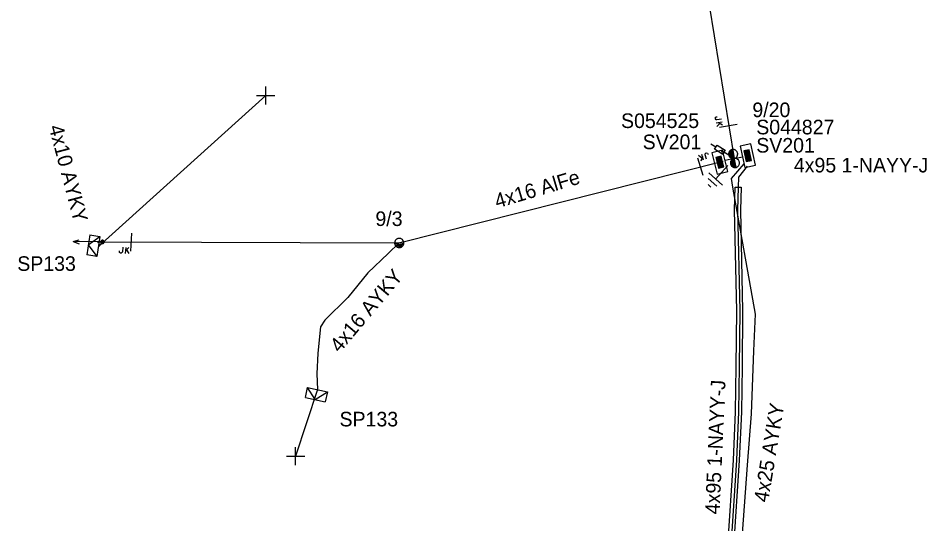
# Model space of a CAD drawing. Extents: x -717562 to -713845, y -1151196 to -1143903.
# Drawn here: x -716997.4 to -716935, y -1145301 to -1145266.3 of the extents above; entities that cross this region are included whole.
import ezdxf

# ---------------------------------------------------------------- set-up
doc = ezdxf.new("R2010")
doc.units = 0
for name, color, linetype in [('Vrstva 1', 7, 'Continuous'), ('Vrstva 12', 7, 'Continuous'), ('Vrstva 13', 7, 'Continuous'), ('Vrstva 14', 7, 'Continuous'), ('Vrstva 15', 7, 'Continuous'), ('Vrstva 16', 7, 'Continuous'), ('Vrstva 18', 7, 'Continuous'), ('Vrstva 2', 7, 'Continuous'), ('Vrstva 20', 7, 'Continuous'), ('Vrstva 28', 7, 'Continuous'), ('Vrstva 29', 7, 'Continuous'), ('Vrstva 30', 7, 'Continuous'), ('Vrstva 31', 7, 'Continuous'), ('Vrstva 33', 7, 'Continuous'), ('Vrstva 34', 7, 'Continuous'), ('Vrstva 5', 7, 'Continuous'), ('Vrstva 52', 7, 'Continuous'), ('Vrstva 54', 7, 'Continuous'), ('Vrstva 59', 7, 'Continuous'), ('Vrstva 6', 7, 'Continuous'), ('Vrstva 8', 7, 'Continuous'), ('Vrstva 9', 7, 'Continuous')]:
    doc.layers.add(name, color=color, linetype=linetype)

# ---------------------------------------------------------------- blocks, each defined once
blk = doc.blocks.new('NN440')
at = {"layer": 'Vrstva 2'}
for points in [[(0.63, 0), (0.63, 0.06), (0.62, 0.13), (0.6, 0.19), (0.58, 0.25), (0.55, 0.31), (0.51, 0.37), (0.47, 0.42), (0.42, 0.46), (0.37, 0.51), (0.32, 0.54), (0.26, 0.57), (0.2, 0.59), (0.13, 0.61), (0.07, 0.62), (0, 0.63), (-0.06, 0.62), (-0.13, 0.61), (-0.19, 0.59), (-0.26, 0.57), (-0.31, 0.54), (-0.37, 0.51), (-0.42, 0.46), (-0.47, 0.42), (-0.51, 0.37), (-0.54, 0.31), (-0.57, 0.25), (-0.6, 0.19), (-0.62, 0.13), (-0.63, 0.06), (-0.63, 0), (-0.63, -0.07), (-0.62, -0.14), (-0.6, -0.2), (-0.57, -0.26), (-0.54, -0.32), (-0.51, -0.37), (-0.47, -0.43), (-0.42, -0.47), (-0.37, -0.51), (-0.31, -0.55), (-0.26, -0.58), (-0.19, -0.6), (-0.13, -0.62), (-0.06, -0.63), (0, -0.63), (0.07, -0.63), (0.13, -0.62), (0.2, -0.6), (0.26, -0.58), (0.32, -0.55), (0.37, -0.51), (0.42, -0.47), (0.47, -0.43), (0.51, -0.37), (0.55, -0.32), (0.58, -0.26), (0.6, -0.2), (0.62, -0.14), (0.63, -0.07), (0.63, 0)], [(-0.63, 0), (0.63, 0)], [(-0.6, -0.18), (0.57, -0.18)], [(-0.51, -0.32), (0.5, -0.32)], [(-0.37, -0.47), (0.35, -0.47)]]:
    blk.add_lwpolyline(points, dxfattribs=at)
blk = doc.blocks.new('NN450')
at = {"layer": 'Vrstva 2'}
for points in [[(0, 0), (0, 0.07), (-0.01, 0.13), (-0.03, 0.19), (-0.05, 0.25), (-0.08, 0.31), (-0.12, 0.37), (-0.16, 0.42), (-0.21, 0.46), (-0.26, 0.51), (-0.31, 0.54), (-0.37, 0.57), (-0.43, 0.59), (-0.5, 0.61), (-0.56, 0.62), (-0.63, 0.62), (-0.69, 0.62), (-0.75, 0.61), (-0.82, 0.59), (-0.88, 0.57), (-0.94, 0.54), (-0.99, 0.51), (-1.04, 0.46), (-1.09, 0.42), (-1.13, 0.37), (-1.17, 0.31), (-1.2, 0.25), (-1.22, 0.19), (-1.24, 0.13), (-1.25, 0.07), (-1.25, 0), (-1.25, -0.07), (-1.24, -0.13), (-1.22, -0.19), (-1.2, -0.25), (-1.17, -0.31), (-1.13, -0.37), (-1.09, -0.42), (-1.04, -0.46), (-0.99, -0.51), (-0.94, -0.54), (-0.88, -0.57), (-0.82, -0.59), (-0.75, -0.61), (-0.69, -0.62), (-0.62, -0.63), (-0.56, -0.62), (-0.5, -0.61), (-0.43, -0.59), (-0.37, -0.57), (-0.31, -0.54), (-0.26, -0.51), (-0.21, -0.46), (-0.16, -0.42), (-0.12, -0.37), (-0.08, -0.31), (-0.05, -0.25), (-0.03, -0.19), (-0.01, -0.13), (0, -0.07), (0, 0)], [(1.25, 0), (1.25, 0.07), (1.24, 0.13), (1.22, 0.19), (1.2, 0.25), (1.17, 0.31), (1.13, 0.37), (1.09, 0.42), (1.04, 0.46), (0.99, 0.51), (0.94, 0.54), (0.88, 0.57), (0.82, 0.59), (0.75, 0.61), (0.69, 0.62), (0.62, 0.62), (0.56, 0.62), (0.5, 0.61), (0.43, 0.59), (0.37, 0.57), (0.31, 0.54), (0.26, 0.51), (0.21, 0.46), (0.16, 0.42), (0.12, 0.37), (0.08, 0.31), (0.05, 0.25), (0.03, 0.19), (0.01, 0.13), (0, 0.07), (0, 0), (0, -0.07), (0.01, -0.13), (0.03, -0.19), (0.05, -0.25), (0.08, -0.31), (0.12, -0.37), (0.16, -0.42), (0.21, -0.46), (0.26, -0.51), (0.31, -0.54), (0.37, -0.57), (0.43, -0.59), (0.5, -0.61), (0.56, -0.62), (0.63, -0.63), (0.69, -0.62), (0.75, -0.61), (0.82, -0.59), (0.88, -0.57), (0.94, -0.54), (0.99, -0.51), (1.04, -0.46), (1.09, -0.42), (1.13, -0.37), (1.17, -0.31), (1.2, -0.25), (1.22, -0.19), (1.24, -0.13), (1.25, -0.07), (1.25, 0)], [(-1.25, 0), (1.25, 0)], [(-1.23, -0.16), (-0.02, -0.16)], [(-1.16, -0.32), (-0.09, -0.32)], [(-1.03, -0.47), (-0.22, -0.47)], [(0.02, -0.16), (1.23, -0.16)], [(0.09, -0.32), (1.16, -0.32)], [(0.22, -0.47), (1.03, -0.47)]]:
    blk.add_lwpolyline(points, dxfattribs=at)
blk = doc.blocks.new('NN560')
at = {"layer": 'Vrstva 2'}
for points in [[(1.999, -0.001), (1.59, 0.141)], [(0, -0.001), (1.999, -0.001)], [(1.999, -0.001), (1.59, -0.134)]]:
    blk.add_lwpolyline(points, dxfattribs=at)
blk = doc.blocks.new('NN840')
at = {"layer": 'Vrstva 15'}
for points in [[(0.003, 0.619), (0.003, -0.631)], [(-0.538, -0.385), (-0.538, -0.71)], [(-0.332, -0.385), (-0.332, -0.798)], [(-0.332, -0.641), (-0.125, -0.385)], [(-0.263, -0.557), (-0.091, -0.798)], [(-0.745, -0.71), (-0.745, -0.66)], [(-0.73, -0.764), (-0.745, -0.71)], [(-0.657, -0.798), (-0.73, -0.764)], [(-0.627, -0.798), (-0.657, -0.798)], [(-0.558, -0.764), (-0.627, -0.798)], [(-0.538, -0.71), (-0.558, -0.764)]]:
    blk.add_lwpolyline(points, dxfattribs=at)
blk = doc.blocks.new('NN800')
at = {"layer": 'Vrstva 1'}
for points in [[(-0.442, 0.442), (0.442, -0.442)], [(-0.442, -0.442), (0.442, 0.442)]]:
    blk.add_lwpolyline(points, dxfattribs=at)
blk = doc.blocks.new('NN820')
at = {"layer": 'Vrstva 13'}
for points in [[(-0.003, 0.004), (-0.003, -1.049)], [(-0.165, -0.813), (0.165, -0.813)], [(-0.165, -1.473), (-0.165, -0.813)], [(-0.003, -1.049), (-0.062, -0.926)], [(-0.003, -1.049), (0.057, -0.926)], [(0.165, -0.813), (0.165, -1.473)], [(0.165, -1.473), (-0.165, -1.473)], [(-0.003, -1.473), (-0.003, -1.871)]]:
    blk.add_lwpolyline(points, dxfattribs=at)
blk = doc.blocks.new('NN620')
at = {"layer": 'Vrstva 8'}
for points in [[(0.752, 0.004), (-0.748, 0.004)], [(-0.748, 0.004), (-0.748, -0.746)], [(0.752, -0.746), (0.752, 0.004)], [(0.368, -0.18), (-0.376, -0.18)], [(-0.376, -0.18), (-0.376, -0.558)], [(-0.376, -0.558), (0.368, -0.558)], [(0.321, -0.227), (-0.329, -0.227)], [(-0.329, -0.227), (-0.329, -0.51)], [(-0.329, -0.51), (0.321, -0.51)], [(0.274, -0.274), (-0.281, -0.274)], [(-0.281, -0.274), (-0.281, -0.463)], [(-0.281, -0.463), (0.274, -0.463)], [(0.227, -0.321), (-0.234, -0.321)], [(-0.234, -0.321), (-0.234, -0.416)], [(-0.234, -0.416), (0.227, -0.416)], [(-0.193, -0.369), (0.185, -0.369)], [(0.227, -0.416), (0.227, -0.321)], [(0.274, -0.463), (0.274, -0.274)], [(0.321, -0.51), (0.321, -0.227)], [(0.368, -0.558), (0.368, -0.18)], [(-0.748, -0.746), (0.752, -0.746)]]:
    blk.add_lwpolyline(points, dxfattribs=at)
blk = doc.blocks.new('NN630')
at = {"layer": 'Vrstva 9'}
for points in [[(-0.003, -0.7), (-0.703, 0)], [(-0.703, -0.7), (-0.703, 0), (0.697, 0), (0.697, -0.7)], [(-0.003, -0.7), (0.697, 0)], [(-0.703, -0.7), (0.697, -0.7)]]:
    blk.add_lwpolyline(points, dxfattribs=at)
blk = doc.blocks.new('NN810')
at = {"layer": 'Vrstva 14'}
for points in [[(0.004, -0.64), (0.004, -1.89)], [(0.629, -1.89), (-0.621, -1.89)], [(0.388, -2.2), (-0.399, -2.2)], [(0.004, -2.515), (-0.124, -2.515)], [(0.137, -2.515), (0.004, -2.515)]]:
    blk.add_lwpolyline(points, dxfattribs=at)
blk = doc.blocks.new('NN500')
at = {"layer": 'Vrstva 2'}
for points in [[(0, -0.24), (0.02, -0.23), (0.05, -0.23), (0.07, -0.22), (0.09, -0.22), (0.12, -0.2), (0.14, -0.19), (0.16, -0.18), (0.17, -0.16), (0.19, -0.14), (0.2, -0.12), (0.21, -0.1), (0.22, -0.07), (0.23, -0.05), (0.23, -0.02), (0.23, 0), (0.23, 0.02), (0.23, 0.05), (0.22, 0.07), (0.21, 0.1), (0.2, 0.12), (0.19, 0.14), (0.17, 0.16), (0.16, 0.17), (0.14, 0.19), (0.12, 0.2), (0.09, 0.21), (0.07, 0.22), (0.05, 0.23), (0.02, 0.23), (0, 0.23), (-0.03, 0.23), (-0.05, 0.23), (-0.07, 0.22), (-0.1, 0.21), (-0.12, 0.2), (-0.14, 0.19), (-0.16, 0.17), (-0.18, 0.16), (-0.19, 0.14), (-0.2, 0.12), (-0.22, 0.1), (-0.22, 0.07), (-0.23, 0.05), (-0.23, 0.02), (-0.24, 0), (-0.23, -0.02), (-0.23, -0.05), (-0.22, -0.07), (-0.22, -0.1), (-0.2, -0.12), (-0.19, -0.14), (-0.18, -0.16), (-0.16, -0.18), (-0.14, -0.19), (-0.12, -0.2), (-0.1, -0.22), (-0.07, -0.22), (-0.05, -0.23), (-0.03, -0.23), (0, -0.24)], [(0, -0.24), (0.02, -0.23), (0.05, -0.23), (0.07, -0.22), (0.09, -0.22), (0.12, -0.2), (0.14, -0.19), (0.16, -0.18), (0.17, -0.16), (0.19, -0.14), (0.2, -0.12), (0.21, -0.1), (0.22, -0.07), (0.23, -0.05), (0.23, -0.02), (0.23, 0), (0.23, 0.02), (0.23, 0.05), (0.22, 0.07), (0.21, 0.1), (0.2, 0.12), (0.19, 0.14), (0.17, 0.16), (0.16, 0.17), (0.14, 0.19), (0.12, 0.2), (0.09, 0.21), (0.07, 0.22), (0.05, 0.23), (0.02, 0.23), (0, 0.23), (-0.03, 0.23), (-0.05, 0.23), (-0.07, 0.22), (-0.1, 0.21), (-0.12, 0.2), (-0.14, 0.19), (-0.16, 0.17), (-0.18, 0.16), (-0.19, 0.14), (-0.2, 0.12), (-0.22, 0.1), (-0.22, 0.07), (-0.23, 0.05), (-0.23, 0.02), (-0.24, 0), (-0.23, -0.02), (-0.23, -0.05), (-0.22, -0.07), (-0.22, -0.1), (-0.2, -0.12), (-0.19, -0.14), (-0.18, -0.16), (-0.16, -0.18), (-0.14, -0.19), (-0.12, -0.2), (-0.1, -0.22), (-0.07, -0.22), (-0.05, -0.23), (-0.03, -0.23), (0, -0.24)], [(0, -0.21), (0.02, -0.2), (0.04, -0.2), (0.06, -0.2), (0.08, -0.19), (0.1, -0.18), (0.12, -0.17), (0.14, -0.15), (0.15, -0.14), (0.16, -0.12), (0.18, -0.1), (0.19, -0.08), (0.19, -0.06), (0.2, -0.04), (0.2, -0.02), (0.2, 0), (0.2, 0.02), (0.2, 0.04), (0.19, 0.06), (0.19, 0.08), (0.18, 0.1), (0.16, 0.12), (0.15, 0.14), (0.14, 0.15), (0.12, 0.17), (0.1, 0.18), (0.08, 0.19), (0.06, 0.19), (0.04, 0.2), (0.02, 0.2), (0, 0.2), (-0.02, 0.2), (-0.04, 0.2), (-0.06, 0.19), (-0.08, 0.19), (-0.1, 0.18), (-0.12, 0.17), (-0.14, 0.15), (-0.15, 0.14), (-0.17, 0.12), (-0.18, 0.1), (-0.19, 0.08), (-0.2, 0.06), (-0.2, 0.04), (-0.21, 0.02), (-0.21, 0), (-0.21, -0.02), (-0.2, -0.04), (-0.2, -0.06), (-0.19, -0.08), (-0.18, -0.1), (-0.17, -0.12), (-0.15, -0.14), (-0.14, -0.15), (-0.12, -0.17), (-0.1, -0.18), (-0.08, -0.19), (-0.06, -0.2), (-0.04, -0.2), (-0.02, -0.2), (0, -0.21)], [(0, -0.18), (0.02, -0.18), (0.04, -0.17), (0.05, -0.17), (0.07, -0.16), (0.09, -0.15), (0.1, -0.14), (0.12, -0.13), (0.13, -0.12), (0.14, -0.1), (0.15, -0.09), (0.16, -0.07), (0.17, -0.05), (0.17, -0.04), (0.17, -0.02), (0.17, 0), (0.17, 0.02), (0.17, 0.04), (0.17, 0.05), (0.16, 0.07), (0.15, 0.09), (0.14, 0.1), (0.13, 0.12), (0.12, 0.13), (0.1, 0.14), (0.09, 0.15), (0.07, 0.16), (0.05, 0.17), (0.04, 0.17), (0.02, 0.17), (0, 0.18), (-0.02, 0.17), (-0.04, 0.17), (-0.06, 0.17), (-0.07, 0.16), (-0.09, 0.15), (-0.1, 0.14), (-0.12, 0.13), (-0.13, 0.12), (-0.14, 0.1), (-0.15, 0.09), (-0.16, 0.07), (-0.17, 0.05), (-0.17, 0.04), (-0.18, 0.02), (-0.18, 0), (-0.18, -0.02), (-0.17, -0.04), (-0.17, -0.05), (-0.16, -0.07), (-0.15, -0.09), (-0.14, -0.1), (-0.13, -0.12), (-0.12, -0.13), (-0.1, -0.14), (-0.09, -0.15), (-0.07, -0.16), (-0.06, -0.17), (-0.04, -0.17), (-0.02, -0.18), (0, -0.18)], [(0, -0.15), (0.01, -0.15), (0.03, -0.14), (0.04, -0.14), (0.06, -0.13), (0.07, -0.13), (0.08, -0.12), (0.1, -0.11), (0.11, -0.1), (0.12, -0.09), (0.13, -0.07), (0.13, -0.06), (0.14, -0.05), (0.14, -0.03), (0.14, -0.02), (0.14, 0), (0.14, 0.01), (0.14, 0.03), (0.14, 0.04), (0.13, 0.06), (0.13, 0.07), (0.12, 0.09), (0.11, 0.1), (0.1, 0.11), (0.08, 0.12), (0.07, 0.13), (0.06, 0.13), (0.04, 0.14), (0.03, 0.14), (0.01, 0.14), (0, 0.15), (-0.02, 0.14), (-0.03, 0.14), (-0.05, 0.14), (-0.06, 0.13), (-0.07, 0.13), (-0.09, 0.12), (-0.1, 0.11), (-0.11, 0.1), (-0.12, 0.09), (-0.13, 0.07), (-0.13, 0.06), (-0.14, 0.04), (-0.14, 0.03), (-0.15, 0.01), (-0.15, 0), (-0.15, -0.02), (-0.14, -0.03), (-0.14, -0.05), (-0.13, -0.06), (-0.13, -0.07), (-0.12, -0.09), (-0.11, -0.1), (-0.1, -0.11), (-0.09, -0.12), (-0.07, -0.13), (-0.06, -0.13), (-0.05, -0.14), (-0.03, -0.14), (-0.02, -0.15), (0, -0.15)], [(0, -0.12), (0.01, -0.12), (0.02, -0.11), (0.03, -0.11), (0.05, -0.11), (0.06, -0.1), (0.07, -0.09), (0.08, -0.09), (0.09, -0.08), (0.09, -0.07), (0.1, -0.06), (0.11, -0.05), (0.11, -0.04), (0.11, -0.02), (0.11, -0.01), (0.12, 0), (0.11, 0.01), (0.11, 0.02), (0.11, 0.04), (0.11, 0.05), (0.1, 0.06), (0.09, 0.07), (0.09, 0.08), (0.08, 0.09), (0.07, 0.09), (0.06, 0.1), (0.05, 0.11), (0.03, 0.11), (0.02, 0.11), (0.01, 0.12), (0, 0.12), (-0.01, 0.12), (-0.03, 0.11), (-0.04, 0.11), (-0.05, 0.11), (-0.06, 0.1), (-0.07, 0.09), (-0.08, 0.09), (-0.09, 0.08), (-0.1, 0.07), (-0.1, 0.06), (-0.11, 0.05), (-0.11, 0.04), (-0.12, 0.02), (-0.12, 0.01), (-0.12, 0), (-0.12, -0.01), (-0.12, -0.02), (-0.11, -0.04), (-0.11, -0.05), (-0.1, -0.06), (-0.1, -0.07), (-0.09, -0.08), (-0.08, -0.09), (-0.07, -0.09), (-0.06, -0.1), (-0.05, -0.11), (-0.04, -0.11), (-0.03, -0.11), (-0.01, -0.12), (0, -0.12)], [(0, -0.09), (0.01, -0.09), (0.02, -0.09), (0.03, -0.08), (0.03, -0.08), (0.04, -0.08), (0.05, -0.07), (0.06, -0.07), (0.06, -0.06), (0.07, -0.05), (0.07, -0.04), (0.08, -0.04), (0.08, -0.03), (0.08, -0.02), (0.09, -0.01), (0.09, 0), (0.09, 0.01), (0.08, 0.02), (0.08, 0.03), (0.08, 0.03), (0.07, 0.04), (0.07, 0.05), (0.06, 0.06), (0.06, 0.06), (0.05, 0.07), (0.04, 0.07), (0.03, 0.08), (0.03, 0.08), (0.02, 0.08), (0.01, 0.09), (0, 0.09), (-0.01, 0.09), (-0.02, 0.08), (-0.03, 0.08), (-0.04, 0.08), (-0.04, 0.07), (-0.05, 0.07), (-0.06, 0.06), (-0.07, 0.06), (-0.07, 0.05), (-0.08, 0.04), (-0.08, 0.03), (-0.08, 0.03), (-0.09, 0.02), (-0.09, 0.01), (-0.09, 0), (-0.09, -0.01), (-0.09, -0.02), (-0.08, -0.03), (-0.08, -0.04), (-0.08, -0.04), (-0.07, -0.05), (-0.07, -0.06), (-0.06, -0.07), (-0.05, -0.07), (-0.04, -0.08), (-0.04, -0.08), (-0.03, -0.08), (-0.02, -0.09), (-0.01, -0.09), (0, -0.09)], [(0, -0.06), (0, -0.06), (0.01, -0.06), (0.02, -0.05), (0.02, -0.05), (0.03, -0.05), (0.03, -0.05), (0.04, -0.04), (0.04, -0.04), (0.05, -0.03), (0.05, -0.03), (0.05, -0.02), (0.05, -0.02), (0.05, -0.01), (0.06, -0.01), (0.06, 0), (0.06, 0.01), (0.05, 0.01), (0.05, 0.02), (0.05, 0.02), (0.05, 0.03), (0.05, 0.03), (0.04, 0.04), (0.04, 0.04), (0.03, 0.05), (0.03, 0.05), (0.02, 0.05), (0.02, 0.05), (0.01, 0.06), (0, 0.06), (0, 0.06), (-0.01, 0.06), (-0.01, 0.06), (-0.02, 0.05), (-0.02, 0.05), (-0.03, 0.05), (-0.03, 0.05), (-0.04, 0.04), (-0.04, 0.04), (-0.05, 0.03), (-0.05, 0.03), (-0.05, 0.02), (-0.06, 0.02), (-0.06, 0.01), (-0.06, 0.01), (-0.06, 0), (-0.06, -0.01), (-0.06, -0.01), (-0.06, -0.02), (-0.05, -0.02), (-0.05, -0.03), (-0.05, -0.03), (-0.04, -0.04), (-0.04, -0.04), (-0.03, -0.05), (-0.03, -0.05), (-0.02, -0.05), (-0.02, -0.05), (-0.01, -0.06), (-0.01, -0.06), (0, -0.06)], [(0, -0.03), (0, -0.03), (0, -0.03), (0.01, -0.03), (0.01, -0.03), (0.01, -0.02), (0.02, -0.02), (0.02, -0.02), (0.02, -0.02), (0.02, -0.02), (0.02, -0.01), (0.02, -0.01), (0.03, -0.01), (0.03, -0.01), (0.03, 0), (0.03, 0), (0.03, 0), (0.03, 0.01), (0.03, 0.01), (0.02, 0.01), (0.02, 0.01), (0.02, 0.02), (0.02, 0.02), (0.02, 0.02), (0.02, 0.02), (0.01, 0.02), (0.01, 0.02), (0.01, 0.03), (0, 0.03), (0, 0.03), (0, 0.03), (0, 0.03), (-0.01, 0.03), (-0.01, 0.03), (-0.01, 0.02), (-0.02, 0.02), (-0.02, 0.02), (-0.02, 0.02), (-0.02, 0.02), (-0.02, 0.02), (-0.03, 0.01), (-0.03, 0.01), (-0.03, 0.01), (-0.03, 0.01), (-0.03, 0), (-0.03, 0), (-0.03, 0), (-0.03, -0.01), (-0.03, -0.01), (-0.03, -0.01), (-0.03, -0.01), (-0.02, -0.02), (-0.02, -0.02), (-0.02, -0.02), (-0.02, -0.02), (-0.02, -0.02), (-0.01, -0.03), (-0.01, -0.03), (-0.01, -0.03), (0, -0.03), (0, -0.03)], [(0.23, 0), (0.7, 0)]]:
    blk.add_lwpolyline(points, dxfattribs=at)

msp = doc.modelspace()

# ---------------------------------------------------------------- linework, layer by layer
at = {"layer": 'Vrstva 1'}
for points in [[(-716957.137, -1145224.189), (-716953.406, -1145244.389), (-716948.267, -1145275.949)], [(-716991.577, -1145281.669), (-716971.226, -1145281.738), (-716949.016, -1145276.138)]]:
    msp.add_lwpolyline(points, dxfattribs=at)
at = {"layer": 'Vrstva 20'}
msp.add_lwpolyline([(-716948.695, -1145302.519), (-716948.306, -1145296.618), (-716948.156, -1145293.303), (-716948.116, -1145290.197), (-716948.077, -1145286.4), (-716948.227, -1145279.478), (-716948.181, -1145277.907), (-716947.782, -1145277.919), (-716947.826, -1145279.48), (-716947.676, -1145286.398), (-716947.717, -1145290.201), (-716947.757, -1145293.315), (-716947.907, -1145296.64), (-716948.298, -1145302.579)], dxfattribs=at)
at = {"layer": 'Vrstva 5'}
for points in [[(-716948.266, -1145275.949), (-716948.872, -1145276.078)], [(-716948.266, -1145275.949), (-716947.69, -1145275.827)], [(-716947.366, -1145276.463), (-716947.957, -1145277.233), (-716947.982, -1145277.913), (-716948.027, -1145279.479), (-716947.877, -1145286.399), (-716947.917, -1145290.199), (-716947.957, -1145293.309), (-716948.107, -1145296.629), (-716948.496, -1145302.549), (-716949.536, -1145306.849), (-716949.996, -1145307.829), (-716951.596, -1145313.789), (-716953.176, -1145318.929), (-716954.097, -1145321.729), (-716954.726, -1145324.959), (-716954.987, -1145326.839), (-716956.566, -1145331.749), (-716957.551, -1145334.03)]]:
    msp.add_lwpolyline(points, dxfattribs=at)
at = {"layer": 'Vrstva 52'}
for points in [[(-716947.589, -1145276.307), (-716948.47, -1145277.33), (-716948.38, -1145277.921), (-716946.817, -1145286.609), (-716946.937, -1145289.139), (-716947.097, -1145293.439), (-716947.356, -1145296.969), (-716947.707, -1145301.649), (-716948.107, -1145306.449), (-716948.176, -1145308.119), (-716947.756, -1145308.469)], [(-716991.576, -1145281.669), (-716991.856, -1145281.978)], [(-716971.226, -1145281.738), (-716971.976, -1145282.459), (-716973.366, -1145283.779), (-716974.756, -1145285.479), (-716976.316, -1145287.029), (-716976.626, -1145287.479), (-716976.796, -1145289.289), (-716976.876, -1145290.719), (-716976.826, -1145291.789)]]:
    msp.add_lwpolyline(points, dxfattribs=at)
at = {"layer": 'Vrstva 59'}
for points in [[(-716991.856, -1145281.979), (-716980.38, -1145271.63)], [(-716976.826, -1145291.789), (-716978.327, -1145296.355)]]:
    msp.add_lwpolyline(points, dxfattribs=at)

# ---------------------------------------------------------------- block references
at = {"layer": 'Vrstva 13'}
for name, p, xscale, yscale, rotation in [('NN450', (-716948.266, -1145275.949), 0.49999999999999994, 0.49999999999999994, -78.61901106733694), ('NN500', (-716991.576, -1145281.669), 0.5, 0.5000000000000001, -168.61899992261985), ('NN440', (-716971.226, -1145281.739), 0.5, 0.49999999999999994, 16.630425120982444)]:
    msp.add_blockref(name, p, dxfattribs=dict(at, xscale=xscale, yscale=yscale, rotation=rotation))
at = {"layer": 'Vrstva 13', "rotation": 179.38473538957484}
msp.add_blockref('NN560', (-716991.578, -1145281.67), dxfattribs=at)
at = {"layer": 'Vrstva 15', "rotation": -42.04566669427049}
msp.add_blockref('NN810', (-716948.266, -1145275.949), dxfattribs=at)
at = {"layer": 'Vrstva 16', "rotation": -121.62375831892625}
msp.add_blockref('NN820', (-716948.266, -1145275.949), dxfattribs=at)
at = {"layer": 'Vrstva 18'}
for p, rotation in [((-716948.651, -1145273.709), -80.25703184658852), ((-716950.559, -1145276.527), -162.80230350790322), ((-716989.624, -1145281.676), -3.6268750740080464)]:
    msp.add_blockref('NN840', p, dxfattribs=dict(at, rotation=rotation))
at = {"layer": 'Vrstva 28'}
for p, rotation in [((-716948.884, -1145276.112), -75.84783588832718), ((-716947.69, -1145275.827), 102.12723815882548)]:
    msp.add_blockref('NN620', p, dxfattribs=dict(at, rotation=rotation))
at = {"layer": 'Vrstva 31'}
for p, rotation in [((-716991.856, -1145281.979), -98.92704720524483), ((-716976.826, -1145291.789), -12.266727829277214)]:
    msp.add_blockref('NN630', p, dxfattribs=dict(at, rotation=rotation))
at = {"layer": 'Vrstva 34', "rotation": 45}
for p in [(-716980.38, -1145271.63), (-716978.327, -1145296.355)]:
    msp.add_blockref('NN800', p, dxfattribs=at)

# ---------------------------------------------------------------- texts
at = {"layer": 'Vrstva 12'}
for s, p in [('9/20', (-716947.009, -1145273.113)), ('9/3', (-716972.855, -1145280.575))]:
    msp.add_text(s, height=1, dxfattribs=at).set_placement(p)
at = {"layer": 'Vrstva 2'}
msp.add_text('4x16 AlFe', height=1, rotation=16.63, dxfattribs=at).set_placement((-716964.514, -1145279.374))
at = {"layer": 'Vrstva 29'}
for s, p in [('S054525', (-716956.014, -1145273.859)), ('S044827', (-716946.741, -1145274.294))]:
    msp.add_text(s, height=1, dxfattribs=at).set_placement(p)
at = {"layer": 'Vrstva 30'}
for p in [(-716954.53, -1145275.309), (-716946.741, -1145275.544)]:
    msp.add_text('SV201', height=1, dxfattribs=at).set_placement(p)
at = {"layer": 'Vrstva 33'}
for p in [(-716997.413, -1145283.651), (-716975.317, -1145294.313)]:
    msp.add_text('SP133', height=1, dxfattribs=at).set_placement(p)
at = {"layer": 'Vrstva 54'}
for s, rotation, p in [('4x10 AYKY', 284.781, (-716995.263, -1145273.782)), ('4x16 AYKY', 49.975, (-716975.309, -1145289.314)), ('4x25 AYKY', 80.62, (-716945.931, -1145299.56))]:
    msp.add_text(s, height=1, rotation=rotation, dxfattribs=at).set_placement(p)
at = {"layer": 'Vrstva 6'}
msp.add_text('4x95 1-NAYY-J', height=1, dxfattribs=at).set_placement((-716944.163, -1145276.905))
msp.add_text('4x95 1-NAYY-J', height=1, rotation=87.413, dxfattribs=at).set_placement((-716949.263, -1145300.352))

doc.saveas('drawing.dxf')
